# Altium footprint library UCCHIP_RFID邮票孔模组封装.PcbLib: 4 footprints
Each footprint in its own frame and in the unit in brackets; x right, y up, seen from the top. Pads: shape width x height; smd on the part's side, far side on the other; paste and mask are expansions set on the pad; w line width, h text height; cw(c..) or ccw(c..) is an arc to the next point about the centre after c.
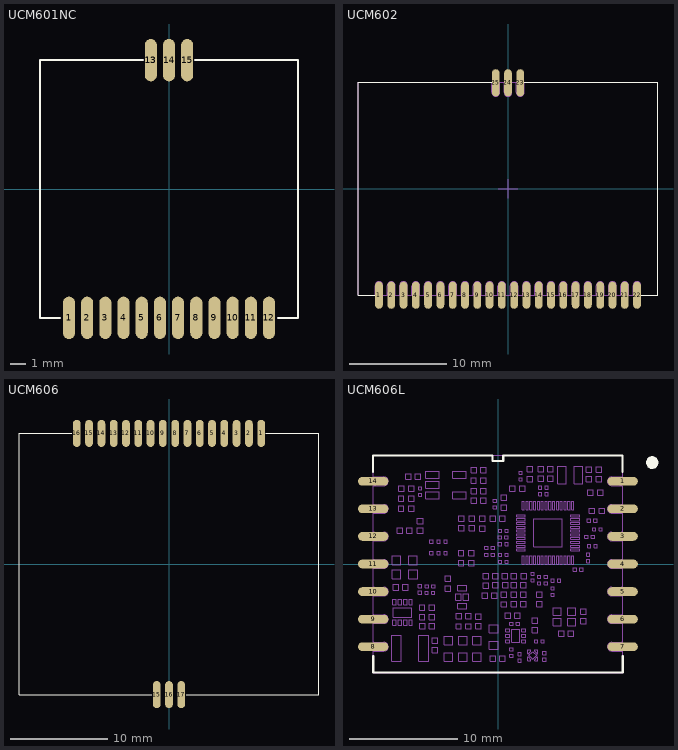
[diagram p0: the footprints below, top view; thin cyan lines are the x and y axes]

## UCM601NC [mm]
pads (16):
  oval 0.8x2.8 smd: 1(-6.6,-8.5) 2(-5.4,-8.5) 3(-4.2,-8.5) 4(-3,-8.5) 5(-1.8,-8.5) 6(-0.6,-8.5) 7(0.6,-8.5) 8(1.8,-8.5) 9(3,-8.5) 10(4.2,-8.5) 11(5.4,-8.5) 12(6.6,-8.5) 13(-1.2,8.5) 13(-1.2,8.5) 14(0,8.5) 15(1.2,8.5)
Top Overlay:
  lines w0.127: -7.2,-8.5 -8.5,-8.5 -8.5,8.5 -1.7,8.5 ; 1.7,8.5 8.5,8.5 8.5,-8.5 7.2,-8.5
3D body: height 1, standoff 0, extent -8.5,-8.5 8.5,8.5

## UCM602 [mm]
pads (25):
  oval 0.8x2.8 smd: 1(-13.335,-11) 2(-12.065,-11) 3(-10.795,-11) 4(-9.525,-11) 5(-8.255,-11) 6(-6.985,-11) 7(-5.715,-11) 8(-4.445,-11) 9(-3.175,-11) 10(-1.905,-11) 11(-0.635,-11) 12(0.635,-11) 13(1.905,-11) 14(3.175,-11) 15(4.445,-11) 16(5.715,-11) 17(6.985,-11) 18(8.255,-11) 19(9.525,-11) 20(10.795,-11) 21(12.065,-11) 22(13.335,-11) 23(1.27,10.95) 24(0,10.95) 25(-1.27,10.95)
Top Overlay:
  lines w0.127: -13.735,-11 -15.5,-11 -15.5,11 -1.667,11 ; 1.667,11 15.5,11 15.5,-11 13.735,-11
Mechanical 5:
  drawing of 214 lines, arcs and shapes, not listed
3D body: height 1.6, standoff 0, extent -15.507,-11.007 15.507,11.007

## UCM606 [mm]
pads (19):
  oval 0.8x2.8 smd: 1(9.525,13.5) 2(8.255,13.5) 3(6.985,13.5) 4(5.715,13.5) 5(4.445,13.5) 6(3.175,13.5) 7(1.905,13.5) 8(0.635,13.5) 9(-0.635,13.5) 10(-1.905,13.5) 11(-3.175,13.5) 12(-4.445,13.5) 13(-5.715,13.5) 14(-6.985,13.5) 15(-8.255,13.5) 15(-1.27,-13.5) 16(-9.525,13.5) 16(0,-13.5) 17(1.27,-13.5)
Top Overlay:
  lines w0.127: -10.058,13.5 -15.5,13.5 -15.5,-13.5 -1.8,-13.5 ; 1.778,-13.5 15.5,-13.5 15.5,13.5 10.02,13.5
3D body: height 1, standoff 0, extent -15.5,-13.5 15.5,13.5

## UCM606L [mm]
pads (14):
  oval 2.8x0.8 smd: 1(11.449,7.62) 2(11.449,5.08) 3(11.449,2.54) 4(11.449,0) 5(11.449,-2.54) 6(11.449,-5.08) 7(11.449,-7.62) 8(-11.538,-7.62) 9(-11.538,-5.08) 10(-11.538,-2.54) 11(-11.538,0) 12(-11.538,2.54) 13(-11.538,5.08) 14(-11.538,7.62)
Top Overlay:
  circle w0.013: c14.173,9.347 r0.536
  region: 14.173,8.811 14.067,8.811 13.87,8.893 13.719,9.044 13.637,9.241 13.637,9.347 13.637,9.454 13.719,9.651 13.87,9.802 14.067,9.883 14.173,9.883 14.28,9.883 14.477,9.802 14.628,9.651 14.709,9.454 14.709,9.347 14.709,9.241 14.628,9.044 14.477,8.893 14.28,8.811
  lines w0.2: -11.551,8.5 -11.551,10 -0.551,10 -0.551,9.5 0.449,9.5 0.449,10 11.449,10 11.449,8.5 ; -11.538,-8.5 -11.538,-10 11.462,-10 11.462,-8.5
Mechanical 5:
  drawing of 1138 lines, arcs and shapes, not listed
3D body: height 0.51, standoff 0, extent -11.551,-10 11.449,10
